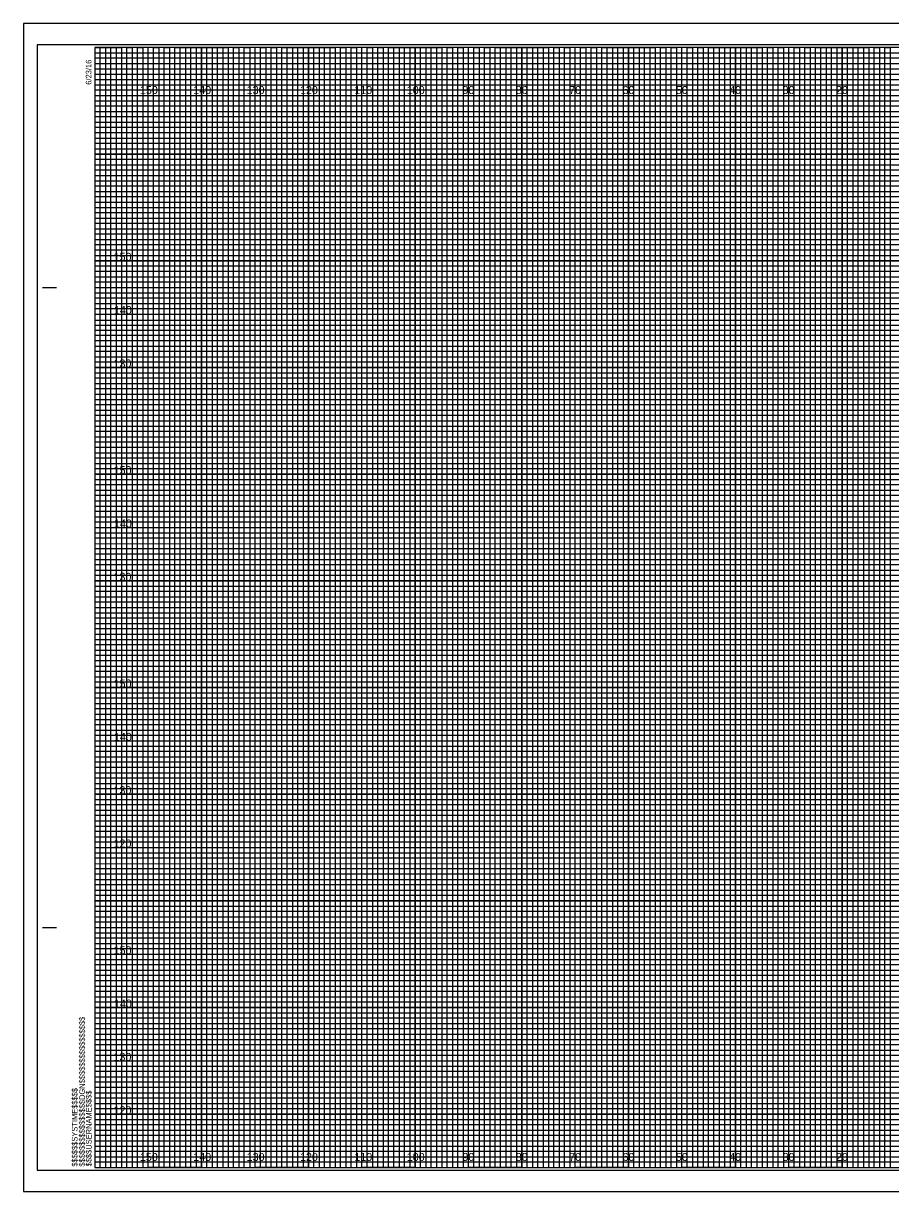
# Model space of a CAD drawing. Extents: x -13 to 323, y -5 to 1094.
# Drawn here: x -13.4 to 149.1, y -4.5 to 214.5 of the extents above; entities that cross this region are included whole.
import ezdxf

# ---------------------------------------------------------------- set-up
doc = ezdxf.new("R2010")
doc.units = 0
for name, color, linetype in [('Exist Cross Section Cell', 7, 'Continuous'), ('Exist XS Center Line Elevation Label', 7, 'Continuous'), ('Exist XS Ground Line', 7, 'Continuous'), ('Prop CMT Pvmt Course 1', 7, 'Continuous'), ('Prop CMT Pvmt Course 3', 7, 'Continuous'), ('Prop CMT Pvmt Surface', 7, 'Continuous'), ('Prop CMT Pvmt Surface Shoulder', 7, 'Continuous'), ('Prop CMT Shld Paved Course 1', 7, 'Continuous'), ('Prop CMT Shld Paved Course 2', 7, 'Continuous'), ('Prop CMT Shld Paved Course 3', 7, 'Continuous'), ('Prop CMT Subgrade Earthwork', 7, 'Continuous')]:
    doc.layers.add(name, color=color, linetype=linetype)

msp = doc.modelspace()

# ---------------------------------------------------------------- linework, layer by layer
at = {"layer": 'Exist XS Center Line Elevation Label'}
for points in [[(0, 210), (5, 210), (5, 0), (15, 0), (15, 210), (25, 210), (25, 0), (35, 0), (35, 210), (45, 210), (45, 0), (55, 0), (55, 210), (65, 210), (65, 0), (75, 0), (75, 210), (85, 210), (85, 0), (95, 0), (95, 210), (105, 210), (105, 0), (115, 0), (115, 210), (125, 210), (125, 0), (135, 0), (135, 210), (145, 210), (145, 0), (155, 0)], [(0, 205), (275, 205)], [(0, 185), (320, 185), (320, 195), (0, 195)], [(0, 165), (320, 165), (320, 175), (0, 175)], [(0, 145), (320, 145), (320, 155), (0, 155)], [(0, 125), (320, 125), (320, 135), (0, 135)], [(0, 105), (320, 105), (320, 115), (0, 115)], [(0, 85), (320, 85), (320, 95), (0, 95)], [(0, 65), (320, 65), (320, 75), (0, 75)], [(0, 45), (320, 45), (320, 55), (0, 55)], [(0, 25), (320, 25), (320, 35), (0, 35)], [(0, 5), (320, 5), (320, 15), (0, 15)]]:
    msp.add_lwpolyline(points, dxfattribs=at)
at = {"layer": 'Exist XS Ground Line'}
for p, q in [((10, 210), (0, 210)), ((10, 0), (10, 210)), ((30, 210), (20, 210)), ((20, 210), (20, 0)), ((30, 0), (30, 210)), ((50, 210), (40, 210)), ((40, 210), (40, 0)), ((50, 0), (50, 210)), ((70, 210), (60, 210)), ((60, 210), (60, 0)), ((70, 0), (70, 210)), ((90, 210), (80, 210)), ((80, 210), (80, 0)), ((90, 0), (90, 210)), ((110, 210), (100, 210)), ((100, 210), (100, 0)), ((110, 0), (110, 210)), ((130, 210), (120, 210)), ((120, 210), (120, 0)), ((130, 0), (130, 210)), ((150, 210), (140, 210)), ((140, 210), (140, 0)), ((20, 0), (10, 0)), ((40, 0), (30, 0)), ((60, 0), (50, 0)), ((80, 0), (70, 0)), ((100, 0), (90, 0)), ((120, 0), (110, 0)), ((140, 0), (130, 0))]:
    msp.add_line(p, q, dxfattribs=at)
for points in [[(0, 200), (320, 200), (320, 190), (0, 190)], [(0, 180), (320, 180), (320, 170), (0, 170)], [(0, 160), (320, 160), (320, 150), (0, 150)], [(0, 140), (320, 140), (320, 130), (0, 130)], [(0, 120), (320, 120), (320, 110), (0, 110)], [(0, 100), (320, 100), (320, 90), (0, 90)], [(0, 80), (320, 80), (320, 70), (0, 70)], [(0, 60), (320, 60), (320, 50), (0, 50)], [(0, 40), (320, 40), (320, 30), (0, 30)], [(0, 20), (320, 20), (320, 10), (0, 10)]]:
    msp.add_lwpolyline(points, dxfattribs=at)
at = {"layer": 'Prop CMT Pvmt Course 3'}
msp.add_lwpolyline([(-13.4, -4.5), (323.3, -4.5), (323.3, 214.5), (-13.4, 214.5)], close=True, dxfattribs=at)
at = {"layer": 'Prop CMT Pvmt Surface'}
for p, q in [((10, 0), (10, 210)), ((20, 0), (20, 210)), ((30, 0), (30, 210)), ((40, 0), (40, 210)), ((50, 0), (50, 210)), ((60, 0), (60, 210)), ((70, 0), (70, 210)), ((80, 0), (80, 210)), ((90, 0), (90, 210)), ((100, 0), (100, 210)), ((110, 0), (110, 210)), ((120, 0), (120, 210)), ((130, 0), (130, 210)), ((140, 0), (140, 210)), ((0, 200), (320, 200)), ((0, 190), (320, 190)), ((0, 180), (320, 180)), ((0, 170), (320, 170)), ((0, 160), (320, 160)), ((0, 150), (320, 150)), ((0, 140), (320, 140)), ((0, 130), (320, 130)), ((0, 120), (320, 120)), ((0, 110), (320, 110)), ((0, 100), (320, 100)), ((0, 90), (320, 90)), ((0, 80), (320, 80)), ((0, 70), (320, 70)), ((0, 60), (320, 60)), ((0, 50), (320, 50)), ((0, 40), (320, 40)), ((0, 30), (320, 30)), ((0, 20), (320, 20)), ((0, 10), (320, 10))]:
    msp.add_line(p, q, dxfattribs=at)
at = {"layer": 'Prop CMT Pvmt Surface Shoulder'}
for p, q in [((323.3, 214.5), (-13.4, 214.5)), ((-13.4, 214.5), (-13.4, -4.5)), ((-13.4, -4.5), (323.3, -4.5))]:
    msp.add_line(p, q, dxfattribs=at)
at = {"layer": 'Prop CMT Shld Paved Course 1'}
for p, q in [((0, 209), (260, 209)), ((260, 207.98), (0, 207.98)), ((0, 207.98), (0, 207)), ((0, 207), (260, 207)), ((260, 205.89), (0, 205.89)), ((0, 205.89), (0, 204)), ((0, 204), (320, 204))]:
    msp.add_line(p, q, dxfattribs=at)
for points in [[(0, 203), (270, 203), (320, 203), (320, 202), (0, 202)], [(0, 201), (320, 201), (320, 199), (0, 199)], [(0, 198), (320, 198), (320, 197), (0, 196.98)], [(0, 196), (320, 196), (320, 194), (0, 194)], [(0, 193), (320, 193), (320, 192), (0, 192)], [(0, 191), (320, 191), (320, 189), (0, 189)], [(0, 188), (320, 188), (320, 187), (0, 187)], [(0, 186), (320, 186), (320, 184), (0, 184)], [(0, 183), (320, 183), (320, 182), (0, 182)], [(0, 181), (320, 181), (320, 179), (0, 179)], [(0, 178), (320, 178), (320, 177), (0, 177)], [(0, 176), (320, 176), (320, 173.95), (320, 173), (320, 172), (0, 172)], [(0, 174), (320, 174), (320, 173), (0, 173)], [(0, 171), (320, 171), (320, 169), (0, 169.03)], [(0, 169.03), (320, 169), (320, 168), (0, 168)], [(0, 167), (320, 167), (320, 166), (0, 166)], [(0, 164), (320, 164), (320, 163), (0, 163)], [(0, 162), (320, 162), (320, 161), (0, 161)], [(-0.07, 158.89), (320, 158.89), (320, 157.88), (-0.07, 157.88)], [(0, 157), (320, 157), (320, 156), (0, 156)], [(0, 154), (320, 154), (320, 153), (0, 153)], [(0, 152), (320, 152), (320, 151), (0, 151)], [(0, 149), (320, 149), (320, 148), (0, 148)], [(0, 147), (320, 147), (320, 146), (0, 146)], [(0, 144), (320, 144), (320, 143), (0, 143)], [(0, 142), (320, 142), (320, 141), (0, 141)], [(0, 139), (320, 139), (319.99, 137.98), (0, 138)], [(0, 137), (320, 137), (320, 136), (0, 136)], [(0, 134), (320, 134), (320, 133), (0, 133)], [(0, 132), (320, 132), (320, 131), (0, 131)], [(0, 129), (320, 129), (320, 128), (0, 128)], [(0, 127), (320, 127), (320, 126), (0, 126)], [(0, 124), (320, 124), (320, 123), (0, 123)], [(0, 122), (320, 122), (320, 121), (0, 121)], [(0, 119), (320, 119), (320, 118), (0, 118)], [(0, 116.99), (320.07, 116.91), (320, 116), (0, 116)], [(0, 114), (320, 114), (320, 113), (0, 113)], [(0, 112), (320, 112), (320, 111), (0, 111)], [(0, 109), (320, 109), (320, 108), (0, 108)], [(0, 107), (320, 107), (320, 106), (0, 106)], [(0, 104), (320, 104), (320, 103), (0, 103)], [(0, 102), (320, 102), (320, 101), (0, 101)], [(0, 99), (320, 99), (320, 98), (0, 98)], [(0, 97), (320, 97), (320, 96), (0, 96)], [(0, 94), (320, 94), (320, 93), (0, 93)], [(0, 92), (320, 92), (320, 91), (0, 91)], [(0, 89), (320, 89), (320, 88), (0, 88)], [(0, 87), (320, 87), (320, 86), (0, 86)], [(0, 84), (320, 84), (320, 83), (0, 83)], [(0, 82), (320, 82), (320, 81), (0, 81)], [(0, 79), (320, 79), (319.99, 77.98), (0, 78)], [(0, 77), (320, 77), (320, 76), (0, 76)], [(0, 74), (320, 74), (320, 73), (0, 73)], [(0, 72), (320, 72), (320, 71), (0, 71)], [(0, 69), (320, 69), (320, 68), (0, 68)], [(0, 67), (320, 67), (320, 66), (0, 66)], [(0, 64), (320, 64), (320, 63), (0, 63)], [(0, 62), (320, 62), (320, 61), (0, 61)], [(0, 59), (320, 59), (320, 58), (0, 58)], [(0, 56.99), (320.07, 56.91), (320, 56), (0, 56)], [(0, 54), (320, 54), (320, 53), (0, 53)], [(0, 52), (320, 52), (320, 51), (0, 51)], [(0, 49), (320, 49), (320, 48), (0, 48)], [(0, 47), (320, 47), (320, 46), (0, 46)], [(0, 44), (320, 44), (320, 43), (0, 43)], [(0, 42), (320, 42), (320, 41), (0, 41)], [(0, 39), (320, 39), (320, 38), (0, 38)], [(0, 37), (320, 37), (320, 36), (0, 36)], [(0, 34), (320, 34), (320, 33), (0, 33)], [(0, 32), (320, 32), (320, 31), (0, 31)], [(0, 29), (320, 29), (320, 28), (0, 28)], [(0, 27), (320, 27), (320, 26), (0, 26)], [(0, 24), (320, 24), (320, 23), (0, 23)], [(0, 22), (320, 22), (320, 21), (0, 21)], [(0, 19), (320, 19), (320, 18), (0, 18)], [(0, 17), (320, 17), (320, 16), (0, 16)], [(0, 14), (320, 14), (320, 13), (0, 13)], [(0, 12), (320, 12), (320, 11), (0, 11)], [(0, 9), (320, 9), (320, 8), (0, 8)], [(0, 7), (320, 7), (320, 6), (0, 6)], [(0, 4), (320, 4), (320, 3), (0, 3)], [(0, 2), (320, 2), (320, 1), (0, 1)]]:
    msp.add_lwpolyline(points, dxfattribs=at)
at = {"layer": 'Prop CMT Shld Paved Course 2'}
for p, q in [((-9.8, 165), (-7.3, 165)), ((-9.7, 165), (-7.2, 165)), ((-9.8, 45), (-7.3, 45)), ((-9.7, 45), (-7.2, 45)), ((0, 0), (0, 0)), ((0, 0), (0, 0)), ((0, 0), (0, 0)), ((0, 0), (0, 0)), ((0, 0), (0, 0)), ((0, 0), (0, 0)), ((0, 0), (0, 0))]:
    msp.add_line(p, q, dxfattribs=at)
msp.add_lwpolyline([(320, 210), (0, 210), (0, 0), (320, 0)], close=True, dxfattribs=at)
at = {"layer": 'Prop CMT Shld Paved Course 3'}
for points in [[(0, 0), (1, 0), (1, 210), (2, 210), (2, 0)], [(2, 0), (3, 0), (3, 210), (4, 210), (4, 0)], [(5, 0), (6, 0), (6, 210), (7, 210), (7, 0)], [(7, 0), (8, 0), (8, 210), (9, 210), (9, 0)], [(10, 0), (11, 0), (11, 210), (12, 210), (12, 0)], [(12, 0), (13, 0), (13, 210), (14, 210), (14, 0)], [(15, 0), (16, 0), (16, 210), (17, 210), (17, 0)], [(17, 0), (18, 0), (18, 210), (19, 210), (19, 0)], [(20, 0), (21, 0), (21, 210), (22, 210), (22, 0)], [(22, 0), (23, 0), (23, 210), (24, 210), (24, 0)], [(25, 0), (26, 0), (26, 210), (27, 210), (27, 0)], [(27, 0), (28, 0), (28, 210), (29, 210), (29, 0)], [(30, 0), (31, 0), (31, 210), (32, 210), (32, 0)], [(32, 0), (33, 0), (33, 210), (34, 210), (34, 0)], [(35, 0), (36, 0), (36, 210), (37, 210), (37, 0)], [(37, 0), (38, 0), (38, 210), (39, 210), (39, 0)], [(40, 0), (41, 0), (41, 210), (42, 210), (42, 0)], [(42, 0), (43, 0), (43, 210), (44, 210), (44, 0)], [(45, 0), (46, 0), (46, 210), (47, 210), (47, 0)], [(47, 0), (48, 0), (48, 210), (49, 210), (49, 0)], [(50, 0), (51, 0), (51, 210), (52, 210), (52, 0)], [(52, 0), (53, 0), (53, 210), (54, 210), (54, 0)], [(55, 0), (56, 0), (56, 210), (57, 210), (57, 0)], [(57, 0), (58, 0), (58, 210), (59, 210), (59, 0)], [(60, 0), (61, 0), (61, 210), (62, 210), (62, 0)], [(62, 0), (63, 0), (63, 210), (64, 210), (64, 0)], [(65, 0), (66, 0), (66, 210), (67, 210), (67, 0)], [(67, 0), (68, 0), (68, 210), (69, 210), (69, 0)], [(70, 0), (71, 0), (71, 210), (72, 210), (72, 0)], [(72, 0), (73, 0), (73, 210), (74, 210), (74, 0)], [(75, 0), (76, 0), (76, 210), (77, 210), (77, 0)], [(77, 0), (78, 0), (78, 210), (79, 210), (79, 0)], [(80, 0), (81, 0), (81, 210), (82, 210), (82, 0)], [(82, 0), (83, 0), (83, 210), (84, 210), (84, 0)], [(85, 0), (86, 0), (86, 210), (87, 210), (87, 0)], [(87, 0), (88, 0), (88, 210), (89, 210), (89, 0)], [(90, 0), (91, 0), (91, 210), (92, 210), (92, 0)], [(92, 0), (93, 0), (93, 210), (94, 210), (94, 0)], [(95, 0), (96, 0), (96, 210), (97, 210), (97, 0)], [(97, 0), (98, 0), (98, 210), (99, 210), (99, 0)], [(100, 0), (101, 0), (101, 210), (102, 210), (102, 0)], [(102, 0), (103, 0), (103, 210), (104, 210), (104, 0)], [(105, 0), (106, 0), (106, 210), (107, 210), (107, 0)], [(107, 0), (108, 0), (108, 210), (109, 210), (109, 0)], [(110, 0), (111, 0), (111, 210), (112, 210), (112, 0)], [(112, 0), (113, 0), (113, 210), (114, 210), (114, 0)], [(115, 0), (116, 0), (116, 210), (117, 210), (117, 0)], [(117, 0), (118, 0), (118, 210), (119, 210), (119, 0)], [(120, 0), (121, 0), (121, 210), (122, 210), (122, 0)], [(122, 0), (123, 0), (123, 210), (124, 210), (124, 0)], [(125, 0), (126, 0), (126, 210), (127, 210), (127, 0)], [(127, 0), (128, 0), (128, 210), (129, 210), (129, 0)], [(130, 0), (131, 0), (131, 210), (132, 210), (132, 0)], [(132, 0), (133, 0), (133, 210), (134, 210), (134, 0)], [(135, 0), (136, 0), (136, 210), (137, 210), (137, 0)], [(137, 0), (138, 0), (138, 210), (139, 210), (139, 0)], [(140, 0), (141, 0), (141, 210), (142, 210), (142, 0)], [(142, 0), (143, 0), (143, 210), (144, 210), (144, 0)], [(145, 0), (146, 0), (146, 210), (147, 210), (147, 0)], [(147, 0), (148, 0), (148, 210), (149, 210), (149, 0)]]:
    msp.add_lwpolyline(points, dxfattribs=at)
at = {"layer": 'Prop CMT Subgrade Earthwork'}
msp.add_lwpolyline([(-10.8, -0.5), (322.4, -0.5), (322.4, 210.5), (-10.8, 210.5)], close=True, dxfattribs=at)

# ---------------------------------------------------------------- texts
at = {"layer": 'Exist Cross Section Cell'}
for s, p in [('150', (8.44, 201.25)), ('140', (18.44, 201.25)), ('130', (28.44, 201.25)), ('120', (38.44, 201.25)), ('110', (48.62, 201.25)), ('100', (58.44, 201.25)), ('90', (68.86, 201.25)), ('80', (78.86, 201.25)), ('70', (88.86, 201.25)), ('60', (98.86, 201.25)), ('50', (108.86, 201.25)), ('40', (118.86, 201.25)), ('30', (128.86, 201.25)), ('20', (138.86, 201.25)), ('150', (8.44, 1.25)), ('140', (18.44, 1.25)), ('130', (28.44, 1.25)), ('120', (38.44, 1.25)), ('110', (48.62, 1.25)), ('100', (58.44, 1.25)), ('90', (68.86, 1.25)), ('80', (78.86, 1.25)), ('70', (88.86, 1.25)), ('60', (98.86, 1.25)), ('50', (108.86, 1.25)), ('40', (118.86, 1.25)), ('30', (128.86, 1.25)), ('20', (138.86, 1.25))]:
    msp.add_text(s, height=1.5, dxfattribs=at).set_placement(p)
at = {"layer": 'Prop CMT Pvmt Course 1'}
for s, p in [('150', (3.52, 170)), ('140', (3.57, 160)), ('130', (3.49, 150)), ('150', (3.52, 130)), ('140', (3.57, 120)), ('130', (3.49, 110)), ('150', (3.52, 90)), ('140', (3.57, 80)), ('130', (3.49, 70)), ('120', (3.5, 60)), ('150', (3.52, 40)), ('140', (3.57, 30)), ('130', (3.49, 20)), ('120', (3.5, 10))]:
    msp.add_text(s, height=1.5, dxfattribs=at).set_placement(p)
at = {"layer": 'Prop CMT Shld Paved Course 2'}
for s, p in [('6/23/16', (-0.65, 203)), ('$$$$$$$$$$$$$$$$DGN$$$$$$$$$$$$$$$$', (-1.88, 0.18)), ('$$$$$$SYSTIME$$$$$', (-3.26, 0.18)), ('$$$$USERNAME$$$$', (-0.62, 0.23))]:
    msp.add_text(s, height=1.05, rotation=90, dxfattribs=at).set_placement(p)

doc.saveas('drawing.dxf')
